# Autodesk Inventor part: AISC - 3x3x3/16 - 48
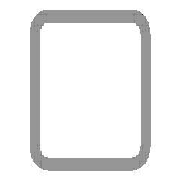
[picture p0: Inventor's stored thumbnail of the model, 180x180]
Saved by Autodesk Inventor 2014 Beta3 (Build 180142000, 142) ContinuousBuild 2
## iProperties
Created: 2011-01
Part Number: AISC - 3x3x3/16 - 48
Material: Steel, Mild
Description: Tube
Document SubType Name: Modeling
Standard: ANSI
Designer: Beta-8540w
Standards Organization: ANSI
Language: en-US
Size Designation: 3x3x3/16
Categories: <MemberInstance><Categories><Category DisplayName="Structural Shapes" InternalName="089c4875-fa83-4c05-b084-43b9cc11f5ed" Mnemonic="GRDR"><CategoryParameter Dis
Stock Number: 3x3x3/16
Density: 7.86 g/cm^3
Appearance: Steel
IsCustomPart: 1
_CCFamilyMember: 9
_CCFamilyDisplayName: ANSI AISC (Square) - Tube
_FrameMemberDoc: Frame Member File
_Version: 15.0.0
_GetPNFromCC: 1
G_L: 48.000 in
G_W: 3.000 in
G_H: 3.000 in
Author: Beta-8540w
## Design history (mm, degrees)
node "Start plane"
node "End plane"
sketch "Sketch"
  geometry: L1 (-38.1, -28.575)-(-38.1, 28.575); L2 (-28.575, 38.1)-(28.575, 38.1); L3 (38.1, 28.575)-(38.1, -28.575); L4 (28.575, -38.1)-(-28.575, -38.1); L5 (-28.575, 33.337)-(28.575, 33.338); L6 (33.338, 28.575)-(33.338, -28.575); L7 (28.575, -33.337)-(-28.575, -33.338); L8 (-33.338, -28.575)-(-33.338, 28.575); L9 (0, 56.102)-(0, -56.102) reference; L10 (-56.102, 0)-(56.102, 0) reference; A1 r 9.525 centre (-28.575, -28.575) between (-38.1, -28.575) and (-28.575, -38.1); A2 r 9.525 centre (-28.575, 28.575) between (-28.575, 38.1) and (-38.1, 28.575); A3 r 9.525 centre (28.575, 28.575) between (38.1, 28.575) and (28.575, 38.1); A4 r 9.525 centre (28.575, -28.575) between (28.575, -38.1) and (38.1, -28.575); A5 r 4.763 centre (-28.575, 28.575) between (-28.575, 33.337) and (-33.338, 28.575); A6 r 4.763 centre (28.575, 28.575) between (33.338, 28.575) and (28.575, 33.338); A7 r 4.763 centre (28.575, -28.575) between (28.575, -33.337) and (33.338, -28.575); A8 r 4.763 centre (-28.575, -28.575) between (-33.338, -28.575) and (-28.575, -33.338)
  constraints: 16 end point, 16 point on circle, 8 centre point, 8 tangent, 4 parallel, 3 equal radius, 2 perpendicular, 7 other
  dimensions: "d10" = 76.2 distance between parallel lines of L2 L4 (= G_H); "d11" = 76.2 distance between parallel lines of L1 L3 (= G_W); "d12" = 4.7625 distance between parallel lines of L3 L6 (= G_T); "d15" = 38.1 distance between parallel lines of L2 L10 (= 0.5 x d10); "d16" = 38.1 distance between parallel lines of L9 L3 (= 0.5 x d11); "d17" = 9.525 radius of A1 (= G_IR)
extrude "Body" new body sketch "Sketch" stored distance "d3" = 1219.2 (= G_L); taper "d4" = 0 deg
node "Driven Length"
  sketch "Sketch3"
    geometry: L1 (0, 0)-(10, 0) reference
    constraints: 2 end point, 1 horizontal
  workplane "Work Plane3"
  sketch "Sketch4"
    geometry: L1 (-2, 0)-(12, 0) reference; L2 (-2, 1219.2)-(12, 1219.2) reference
    dimensions: "d19" = 1219.2 distance between parallel lines of L1 L2 (derived)
body "Solid1"
other parameters: "G_W" = 76.2 [user parameter; used in 1 equation term], "G_H" = 76.2 [user parameter; used in 1 equation term], "G_T" = 4.7625 [user parameter; used in 1 equation term], "G_IR" = 9.525 [user parameter; used in 1 equation term], "G_L" = 1219.2 (= d19) [user parameter; used in 1 equation term], "G_OFFSET_START" = 0 [user parameter; used in 1 equation term], "G_OFFSET_END" = 0 [user parameter; used in 1 equation term], "d13" = 0 (computed from G_OFFSET_START), "d14" = 1219.2 (= G_OFFSET_END + B_L), "B_L" = 1219.2 [user parameter; used in 1 equation term], "d18" = 90 deg
